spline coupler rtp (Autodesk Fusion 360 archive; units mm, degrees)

design "spline coupler rtp" references "Haas UMC-750 NGC"
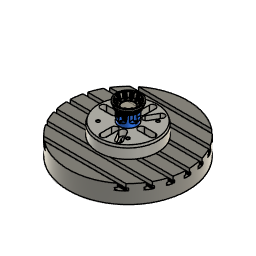
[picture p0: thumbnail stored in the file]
sketch "Sketch1" plane through (0, 0, 0) normal (1, 0, 0) x axis (0, 1, 0)
  line L1 (50.8, 0) -> (0, 0)
  line L2 (50.8, 25.4) -> (50.8, 0)
  line L3 (44.45, 25.4) -> (50.8, 25.4)
  line L4 (37.5164, 6.35) -> (44.45, 25.4)
  line L5 (0, 6.35) -> (37.5164, 6.35)
  line L6 (0, 0) -> (0, 6.35)
  line L7 (50.8, 19.05) -> (50.8, 25.4)
  line L8 (43.8664, 0) -> (50.8, 19.05)
  line L9 (48.0144, 13.7174) -> (48.4888, 12.7)
  line L10 (49.0317, 14.1918) -> (48.0144, 13.7174)
  line L11 (48.7603, 13.4459) -> (48.0144, 13.7174)
  line L12 (46.1776, 6.35) -> (47.0031, 6.35)
  circle C1 centre (48.9975, 12.9372) radius 0.5613
  circle C2 centre (47.0031, 6.35) radius 1.5875
  point P1 (0, 0)
  point P2 (0, 0)
  point P8 (0, 0)
  point P9 (50.8, 19.05)
  point P10 (43.8664, 0)
  point P11 (48.4888, 12.7)
  point P13 (49.0317, 14.1918)
  point P14 (48.7603, 13.4459)
  point P16 (48.4888, 12.7)
  point P17 (48.7603, 13.4459)
  point P18 (47.0031, 6.35)
  point P19 (47.0031, 6.35)
  point P20 (46.1776, 6.35)
  point P3 (50.8, 0)
  point P4 (50.8, 25.4)
  point P7 (0, 6.35)
  point P12 (48.0144, 13.7174)
  point P5 (44.45, 25.4)
  coincident P1 P2
  horizontal L1
  perpendicular L1 L2
  perpendicular L2 L3
  parallel L1 L5
  coincident P1 P8
  vertical L6
  coincident L2 P9
  coincident L1 P10
  parallel L4 L8
  coincident L8 P11
  coincident L8 P13
  perpendicular L9 L10
  equal L9 L10
  coincident L8 P14
  perpendicular L8 L11
  coincident C1 P16
  coincident L8 P16
  coincident P11 P16
  coincident C1 P17
  coincident P14 P17
  tangent L9 C1
  coincident P18 P19
  coincident L8 P20
  horizontal L12
  dimension "d2" = 88.9
  dimension "d3" distance P3 P4 = 25.4
  dimension "d4" angle L3 L4 = 70
  dimension "d5" distance P7 P8 = 6.35
  dimension "d37" distance P4 P9 = 6.35
  dimension "d38" distance P12 P14 = 0.7937
  dimension "d39" distance P10 P11 = 12.7
  dimension "d40" distance P4 P5 = 6.35
  dimension "d43" diameter C2 = 3.175
  dimension "d44" distance L1 P18 = 6.35
  dimension "d45" distance P19 P20 = 0.8255
revolve "Revolve1" sketch "Sketch1" AlongAngle 360
work_plane "WorkPlane1" AlongDistance -3.175
sketch "Sketch2" plane through (0, 0, 22.225) normal (0, 0, 1) x axis (1, 0, 0)
  line L1 (0, 36.9444) -> (0, 0)
  line L2 (3.175, 36.9444) -> (-3.175, 36.9444)
  line L3 (3.175, 32.5535) -> (3.175, 36.9444)
  circle C1 centre (0, 0) radius 43.2944
  circle C2 centre (0, 0) radius 36.9444
  arc A1 centre (10.795, 36.9444) radius 7.62 clockwise from (3.175, 36.9444) to (6.0106, 42.8751)
  arc A2 centre (-10.795, 36.9444) radius 7.62 clockwise from (-6.0106, 42.8751) to (-3.175, 36.9444)
  point P2 (0, 0)
  point P4 (0, 0)
  point P5 (0, 36.9444)
  point P8 (6.0106, 42.8751)
  point P7 (3.175, 36.9444)
  point P13 (-3.175, 36.9444)
  point P12 (-6.0106, 42.8751)
  point P6 (-3.175, 36.9444)
  coincident P2 P4
  coincident C2 P5
  vertical L1
  perpendicular L1 L2
  midpoint P5 L2
  coincident C1 P8
  perpendicular L2 L3
  tangent A1 L3
  symmetric L1 P7 P13
  symmetric L1 P8 P12
  symmetric L1 A1 A2
  dimension "d8" = 6.35
  dimension "d9" distance P6 P7 = 6.35
  dimension "d10" radius A1 = 7.62
sketch "Sketch3" plane through (0, 0, 22.225) normal (0, 0, 1) x axis (1, 0, 0)
sketch "Sketch4" plane through (0, 0, 0) normal (1, 0, 0) x axis (0, 1, 0)
  line L1 (37.5164, 6.35) -> (44.45, 25.4)
  line L2 (-44.45, 25.4) -> (-37.5164, 6.35)
  line L3 (36.9444, 22.225) -> (0, 22.225)
  line L4 (31.1664, 6.35) -> (36.9444, 22.225)
  line L5 (-37.5164, 6.35) -> (37.5164, 6.35)
  point P7 (36.9444, 22.225)
  point P8 (36.9444, 22.225)
  point P9 (31.1664, 6.35)
  coincident P7 P8
  coincident P9 L5
  parallel L1 L4
copy_paste_bodies "CopyPasteBodies2"
sweep "Sweep1" sketch "Sketch2" TwistAngle 0 TaperAngle 0
fillet "Fillet1" sketch "Sketch1" radius 1.5875
fillet "Fillet5" sketch "Sketch1" radius 1.5875
circular_pattern "C-Pattern1" countU 12 TotalAngle 360
fillet "Fillet2" radius 1.5875
fillet "Fillet4" radius 1.5875
sketch "Sketch5" plane through (0, 0, 6.35) normal (0, 0, 1) x axis (-1, 0, 0)
  curve K1 (12.3507, -34.2457) -> (12.1885, -30.8252)
  line L1 (16.5345, -25.1581) -> (13.5203, -26.8984)
  curve K2 (20.6012, -25.9681) -> (23.4823, -27.8189)
  curve K3 (27.8189, -23.4823) -> (25.9681, -20.6012)
  line L2 (26.8984, -13.5203) -> (25.1581, -16.5345)
  curve K4 (30.8252, -12.1885) -> (34.2457, -12.3507)
  curve K5 (35.833, -6.4268) -> (32.7897, -4.8571)
  line L3 (30.0548, 1.7403) -> (30.0548, -1.7403)
  curve K6 (32.7897, 4.8571) -> (35.833, 6.4268)
  curve K7 (34.2457, 12.3507) -> (30.8252, 12.1885)
  line L4 (25.1581, 16.5345) -> (26.8984, 13.5203)
  curve K8 (25.9681, 20.6012) -> (27.8189, 23.4823)
  curve K9 (23.4823, 27.8189) -> (20.6012, 25.9681)
  line L5 (13.5203, 26.8984) -> (16.5345, 25.1581)
  curve K10 (12.1885, 30.8252) -> (12.3507, 34.2457)
  curve K11 (6.4268, 35.833) -> (4.8571, 32.7897)
  line L6 (-1.7403, 30.0548) -> (1.7403, 30.0548)
  curve K12 (-4.8571, 32.7897) -> (-6.4268, 35.833)
  curve K13 (-12.3507, 34.2457) -> (-12.1885, 30.8252)
  line L7 (-16.5345, 25.1581) -> (-13.5203, 26.8984)
  curve K14 (-20.6012, 25.9681) -> (-23.4823, 27.8189)
  curve K15 (-27.8189, 23.4823) -> (-25.9681, 20.6012)
  line L8 (-26.8984, 13.5203) -> (-25.1581, 16.5345)
  curve K16 (-30.8252, 12.1885) -> (-34.2457, 12.3507)
  curve K17 (-35.833, 6.4268) -> (-32.7897, 4.8571)
  line L9 (-30.0548, -1.7403) -> (-30.0548, 1.7403)
  curve K18 (-32.7897, -4.8571) -> (-35.833, -6.4268)
  curve K19 (-34.2457, -12.3507) -> (-30.8252, -12.1885)
  line L10 (-25.1581, -16.5345) -> (-26.8984, -13.5203)
  curve K20 (-25.9681, -20.6012) -> (-27.8189, -23.4823)
  curve K21 (-23.4823, -27.8189) -> (-20.6012, -25.9681)
  line L11 (-13.5203, -26.8984) -> (-16.5345, -25.1581)
  curve K22 (-12.1885, -30.8252) -> (-12.3507, -34.2457)
  curve K23 (-6.4268, -35.833) -> (-4.8571, -32.7897)
  line L12 (1.7403, -30.0548) -> (-1.7403, -30.0548)
  curve K24 (4.8571, -32.7897) -> (6.4268, -35.833)
  closed curve K25 centre (15.2096, -29.8245)
  closed curve K26 centre (18.2239, -28.0842)
  arc A1 centre (0, 0) radius 36.4048 clockwise from (27.8189, -23.4823) to (23.4823, -27.8189)
  closed curve K27 centre (28.0842, -18.2239)
  closed curve K28 centre (29.8245, -15.2096)
  arc A2 centre (0, 0) radius 36.4048 clockwise from (35.833, -6.4268) to (34.2457, -12.3507)
  closed curve K29 centre (33.4336, -1.7403)
  closed curve K30 centre (33.4336, 1.7403)
  arc A3 centre (0, 0) radius 36.4048 clockwise from (34.2457, 12.3507) to (35.833, 6.4268)
  closed curve K31 centre (29.8245, 15.2096)
  closed curve K32 centre (28.0842, 18.2239)
  arc A4 centre (0, 0) radius 36.4048 clockwise from (23.4823, 27.8189) to (27.8189, 23.4823)
  closed curve K33 centre (18.2239, 28.0842)
  closed curve K34 centre (15.2096, 29.8245)
  arc A5 centre (0, 0) radius 36.4048 clockwise from (6.4268, 35.833) to (12.3507, 34.2457)
  closed curve K35 centre (1.7403, 33.4336)
  closed curve K36 centre (-1.7403, 33.4336)
  arc A6 centre (0, 0) radius 36.4048 clockwise from (-12.3507, 34.2457) to (-6.4268, 35.833)
  closed curve K37 centre (-15.2096, 29.8245)
  closed curve K38 centre (-18.2239, 28.0842)
  arc A7 centre (0, 0) radius 36.4048 clockwise from (-27.8189, 23.4823) to (-23.4823, 27.8189)
  closed curve K39 centre (-28.0842, 18.2239)
  closed curve K40 centre (-29.8245, 15.2096)
  arc A8 centre (0, 0) radius 36.4048 clockwise from (-35.833, 6.4268) to (-34.2457, 12.3507)
  closed curve K41 centre (-33.4336, 1.7403)
  closed curve K42 centre (-33.4336, -1.7403)
  arc A9 centre (0, 0) radius 36.4048 clockwise from (-34.2457, -12.3507) to (-35.833, -6.4268)
  closed curve K43 centre (-29.8245, -15.2096)
  closed curve K44 centre (-28.0842, -18.2239)
  arc A10 centre (0, 0) radius 36.4048 clockwise from (-23.4823, -27.8189) to (-27.8189, -23.4823)
  closed curve K45 centre (-18.2239, -28.0842)
  closed curve K46 centre (-15.2096, -29.8245)
  arc A11 centre (0, 0) radius 36.4048 clockwise from (-6.4268, -35.833) to (-12.3507, -34.2457)
  closed curve K47 centre (-1.7403, -33.4336)
  closed curve K48 centre (1.7403, -33.4336)
  arc A12 centre (0, 0) radius 36.4048 clockwise from (12.3507, -34.2457) to (6.4268, -35.833)
  circle C1 centre (0, 0) radius 25.4
  concentric A1 C1
  dimension "d29" diameter C1 = 50.8
extrude "Extrude1" cut sketch "Sketch5" profile of C1 against normal blind 3.175
chamfer "Chamfer1" sketch "Sketch1" distance 0.7937
fillet "Fillet6" sketch "Sketch1" radius 1.5875
delete_face "DeleteFace1"
delete_face "DeleteFace2"
delete_face "DeleteFace3"
derived_base_feature "Derived Base Feature1" bodies "Dovetail"
move "Move1"
offset_faces "OffsetFaces1" distance -25.4
move "Move2"
align "Align1"
combine "Combine2" bodies "Dovetail"
derived_base_feature "Derived Base Feature1" bodies "Body1"
base_feature "Base Feature1"
joint "Assemble1" alignAngle 0 alignOffsetX 0 named "d2_1" alignOffsetY 0 named "d3_1" alignOffsetZ 0 named "d4_1"
base_feature "Base Feature1" bodies "Body1", "Body2", "Body3", "Body4", "Body5", "Body6"
joint "Assemble2" alignAngle 0 named "d5_1" alignOffsetX 0 named "d6_1" alignOffsetY 0 named "d7_1" alignOffsetZ 0 named "d8_1"
joint "Assemble1" alignAngle 0 alignOffsetX 0 alignOffsetY 0 alignOffsetZ 0
sketch "Sketch7" plane through (0, 0, 0) normal (1, 0, 0) x axis (0, 1, 0)
  line L1 (-251.1903, -101.5746) -> (-198.6319, -101.5746)
  point P1 (0, 0)
  point P2 (0, -355.5746)
  vertical P1 P2
  dimension "d51" distance P2 L1 = 254
work_point "WorkPoint1"
sketch "Dovetail" plane through (0, 0, 0) normal (1, 0, 0) x axis (0, 1, 0)
  line L1 (-18.5336, -2.3876) -> (-17.1551, 0)
  line L2 (-18.5336, -3.1496) -> (-18.5336, -2.3876)
  line L3 (-23.5051, 0) -> (-17.1551, 0)
  line L4 (-23.5051, -50.8) -> (-23.5051, 0)
  line L5 (-18.5336, -50.8) -> (-23.5051, -50.8)
  line L6 (-18.5336, -3.1496) -> (-18.5336, -50.8)
  point P2 (-17.1551, 0)
  point P6 (-17.1551, 0)
  point P5 (-18.5336, -3.1496)
  point P10 (-18.5336, -3.1496)
  point P7 (-23.5051, 0)
  point P8 (-23.5051, -50.8)
  coincident P2 P6
  horizontal L3
  perpendicular L3 L4
  perpendicular L4 L5
  coincident P5 P10
  vertical L6
  dimension "d52" = 12.7
  dimension "d53" distance P7 P8 = 50.8
sketch "Sketch9" plane through (0, 0, 0) normal (1, 0, 0) x axis (0, 1, 0)
  line L1 (31.5465, 7.3945) -> (36.5642, 21.1805)
revolve "Revolve3" AlongAngle 360
component_insert "Component Insert"
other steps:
base_feature "Base Feature2" bodies "Stock"
joint_origin "JointOrigin1"
create_component "CreateComponent1"
joint_origin "JointOrigin1"
create_component "CreateComponent2"
create_component "CreateComponent2"
create_component "CreateComponent3"
named bodies: "Part", "Stock", "Dovetail", "Body1", "Body2", "Body3", "Body4", "Body5", "Body6"

design "Haas UMC-750 NGC"
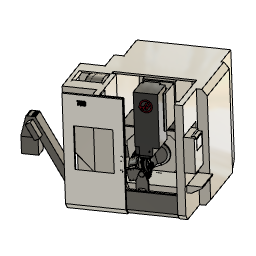
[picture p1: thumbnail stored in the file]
base_feature "Base Feature1"
base_feature "Base Feature1"
base_feature "Base Feature1"
base_feature "Base Feature1"
base_feature "Base Feature1"
base_feature "Base Feature1"
base_feature "Base Feature1"
base_feature "Base Feature1"
base_feature "Base Feature1" bodies "Body1"
base_feature "Base Feature1"
base_feature "Base Feature1" bodies "Body1", "Body2", "Body3", "Body4", "Body5", "Body6"
joint "Assemble1" alignAngle 0 alignOffsetX 0 alignOffsetY 0 alignOffsetZ 0
joint "Assemble2" alignAngle 0 alignOffsetX 0 alignOffsetY 0 alignOffsetZ 0
as_built_joint "As-built1"
as_built_joint "As-built2" OffsetX 0 OffsetY 0 OffsetZ 0 AngleZ 0
as_built_joint "As-built3" OffsetX 0 OffsetY 0 OffsetZ 0 AngleZ 0
ground "Ground1"
ground "Ground2"
sketch "Sketch1" plane through (0, 0, 0) normal (1, 0, 0) x axis (0, 1, 0)
  line L1 (50.8, 0) -> (0, 0)
  line L2 (50.8, 25.4) -> (50.8, 0)
  line L3 (44.45, 25.4) -> (50.8, 25.4)
  line L4 (37.5164, 6.35) -> (44.45, 25.4)
  line L5 (0, 6.35) -> (37.5164, 6.35)
  line L6 (0, 0) -> (0, 6.35)
  line L7 (50.8, 19.05) -> (50.8, 25.4)
  line L8 (43.8664, 0) -> (50.8, 19.05)
  line L9 (48.0144, 13.7174) -> (48.4888, 12.7)
  line L10 (49.0317, 14.1918) -> (48.0144, 13.7174)
  line L11 (48.7603, 13.4459) -> (48.0144, 13.7174)
  line L12 (46.1776, 6.35) -> (47.0031, 6.35)
  circle C1 centre (48.9975, 12.9372) radius 0.5613
  circle C2 centre (47.0031, 6.35) radius 1.5875
  point P1 (0, 0)
  point P2 (0, 0)
  point P8 (0, 0)
  point P9 (50.8, 19.05)
  point P10 (43.8664, 0)
  point P11 (48.4888, 12.7)
  point P13 (49.0317, 14.1918)
  point P14 (48.7603, 13.4459)
  point P16 (48.4888, 12.7)
  point P17 (48.7603, 13.4459)
  point P18 (47.0031, 6.35)
  point P19 (47.0031, 6.35)
  point P20 (46.1776, 6.35)
  point P3 (50.8, 0)
  point P4 (50.8, 25.4)
  point P7 (0, 6.35)
  point P12 (48.0144, 13.7174)
  point P5 (44.45, 25.4)
  coincident P1 P2
  horizontal L1
  perpendicular L1 L2
  perpendicular L2 L3
  parallel L1 L5
  coincident P1 P8
  vertical L6
  coincident L2 P9
  coincident L1 P10
  parallel L4 L8
  coincident L8 P11
  coincident L8 P13
  perpendicular L9 L10
  equal L9 L10
  coincident L8 P14
  perpendicular L8 L11
  coincident C1 P16
  coincident L8 P16
  coincident P11 P16
  coincident C1 P17
  coincident P14 P17
  tangent L9 C1
  coincident P18 P19
  coincident L8 P20
  horizontal L12
  dimension "d2_1" = 88.9
  dimension "d3_1" distance P3 P4 = 25.4
  dimension "d4_1" angle L3 L4 = 70
  dimension "d5_1" distance P7 P8 = 6.35
  dimension "d37" distance P4 P9 = 6.35
  dimension "d38" distance P12 P14 = 0.7937
  dimension "d39" distance P10 P11 = 12.7
  dimension "d40" distance P4 P5 = 6.35
  dimension "d43" diameter C2 = 3.175
  dimension "d44" distance L1 P18 = 6.35
  dimension "d45" distance P19 P20 = 0.8255
revolve "Revolve1" sketch "Sketch1" AlongAngle 360 named "d6_1"
work_plane "WorkPlane1" AlongDistance -3.175 named "d7_1"
sketch "Sketch2" plane through (0, 0, 22.225) normal (0, 0, 1) x axis (1, 0, 0)
  line L1 (0, 36.9444) -> (0, 0)
  line L2 (3.175, 36.9444) -> (-3.175, 36.9444)
  line L3 (3.175, 32.5535) -> (3.175, 36.9444)
  circle C1 centre (0, 0) radius 43.2944
  circle C2 centre (0, 0) radius 36.9444
  arc A1 centre (10.795, 36.9444) radius 7.62 clockwise from (3.175, 36.9444) to (6.0106, 42.8751)
  arc A2 centre (-10.795, 36.9444) radius 7.62 clockwise from (-6.0106, 42.8751) to (-3.175, 36.9444)
  point P2 (0, 0)
  point P4 (0, 0)
  point P5 (0, 36.9444)
  point P8 (6.0106, 42.8751)
  point P7 (3.175, 36.9444)
  point P13 (-3.175, 36.9444)
  point P12 (-6.0106, 42.8751)
  point P6 (-3.175, 36.9444)
  coincident P2 P4
  coincident C2 P5
  vertical L1
  perpendicular L1 L2
  midpoint P5 L2
  coincident C1 P8
  perpendicular L2 L3
  tangent A1 L3
  symmetric L1 P7 P13
  symmetric L1 P8 P12
  symmetric L1 A1 A2
  dimension "d8_1" = 6.35
  dimension "d9_1" distance P6 P7 = 6.35
  dimension "d10_1" radius A1 = 7.62
sketch "Sketch3" plane through (0, 0, 22.225) normal (0, 0, 1) x axis (1, 0, 0)
sketch "Sketch4" plane through (0, 0, 0) normal (1, 0, 0) x axis (0, 1, 0)
  line L1 (37.5164, 6.35) -> (44.45, 25.4)
  line L2 (-44.45, 25.4) -> (-37.5164, 6.35)
  line L3 (36.9444, 22.225) -> (0, 22.225)
  line L4 (31.1664, 6.35) -> (36.9444, 22.225)
  line L5 (-37.5164, 6.35) -> (37.5164, 6.35)
  point P7 (36.9444, 22.225)
  point P8 (36.9444, 22.225)
  point P9 (31.1664, 6.35)
  coincident P7 P8
  coincident P9 L5
  parallel L1 L4
copy_paste_bodies "CopyPasteBodies2"
sweep "Sweep1" sketch "Sketch2" TwistAngle 0 named "d15_1" TaperAngle 0 named "d16_1"
fillet "Fillet1" radius 1.5875
fillet "Fillet5" radius 1.5875
circular_pattern "C-Pattern1" countU 12 TotalAngle 360
fillet "Fillet2" radius 1.5875
fillet "Fillet4" radius 1.5875
sketch "Sketch5" plane through (0, 0, 6.35) normal (0, 0, 1) x axis (-1, 0, 0)
  curve K1 (12.3507, -34.2457) -> (12.1885, -30.8252)
  line L1 (16.5345, -25.1581) -> (13.5203, -26.8984)
  curve K2 (20.6012, -25.9681) -> (23.4823, -27.8189)
  curve K3 (27.8189, -23.4823) -> (25.9681, -20.6012)
  line L2 (26.8984, -13.5203) -> (25.1581, -16.5345)
  curve K4 (30.8252, -12.1885) -> (34.2457, -12.3507)
  curve K5 (35.833, -6.4268) -> (32.7897, -4.8571)
  line L3 (30.0548, 1.7403) -> (30.0548, -1.7403)
  curve K6 (32.7897, 4.8571) -> (35.833, 6.4268)
  curve K7 (34.2457, 12.3507) -> (30.8252, 12.1885)
  line L4 (25.1581, 16.5345) -> (26.8984, 13.5203)
  curve K8 (25.9681, 20.6012) -> (27.8189, 23.4823)
  curve K9 (23.4823, 27.8189) -> (20.6012, 25.9681)
  line L5 (13.5203, 26.8984) -> (16.5345, 25.1581)
  curve K10 (12.1885, 30.8252) -> (12.3507, 34.2457)
  curve K11 (6.4268, 35.833) -> (4.8571, 32.7897)
  line L6 (-1.7403, 30.0548) -> (1.7403, 30.0548)
  curve K12 (-4.8571, 32.7897) -> (-6.4268, 35.833)
  curve K13 (-12.3507, 34.2457) -> (-12.1885, 30.8252)
  line L7 (-16.5345, 25.1581) -> (-13.5203, 26.8984)
  curve K14 (-20.6012, 25.9681) -> (-23.4823, 27.8189)
  curve K15 (-27.8189, 23.4823) -> (-25.9681, 20.6012)
  line L8 (-26.8984, 13.5203) -> (-25.1581, 16.5345)
  curve K16 (-30.8252, 12.1885) -> (-34.2457, 12.3507)
  curve K17 (-35.833, 6.4268) -> (-32.7897, 4.8571)
  line L9 (-30.0548, -1.7403) -> (-30.0548, 1.7403)
  curve K18 (-32.7897, -4.8571) -> (-35.833, -6.4268)
  curve K19 (-34.2457, -12.3507) -> (-30.8252, -12.1885)
  line L10 (-25.1581, -16.5345) -> (-26.8984, -13.5203)
  curve K20 (-25.9681, -20.6012) -> (-27.8189, -23.4823)
  curve K21 (-23.4823, -27.8189) -> (-20.6012, -25.9681)
  line L11 (-13.5203, -26.8984) -> (-16.5345, -25.1581)
  curve K22 (-12.1885, -30.8252) -> (-12.3507, -34.2457)
  curve K23 (-6.4268, -35.833) -> (-4.8571, -32.7897)
  line L12 (1.7403, -30.0548) -> (-1.7403, -30.0548)
  curve K24 (4.8571, -32.7897) -> (6.4268, -35.833)
  closed curve K25 centre (15.2096, -29.8245)
  closed curve K26 centre (18.2239, -28.0842)
  arc A1 centre (0, 0) radius 36.4048 clockwise from (27.8189, -23.4823) to (23.4823, -27.8189)
  closed curve K27 centre (28.0842, -18.2239)
  closed curve K28 centre (29.8245, -15.2096)
  arc A2 centre (0, 0) radius 36.4048 clockwise from (35.833, -6.4268) to (34.2457, -12.3507)
  closed curve K29 centre (33.4336, -1.7403)
  closed curve K30 centre (33.4336, 1.7403)
  arc A3 centre (0, 0) radius 36.4048 clockwise from (34.2457, 12.3507) to (35.833, 6.4268)
  closed curve K31 centre (29.8245, 15.2096)
  closed curve K32 centre (28.0842, 18.2239)
  arc A4 centre (0, 0) radius 36.4048 clockwise from (23.4823, 27.8189) to (27.8189, 23.4823)
  closed curve K33 centre (18.2239, 28.0842)
  closed curve K34 centre (15.2096, 29.8245)
  arc A5 centre (0, 0) radius 36.4048 clockwise from (6.4268, 35.833) to (12.3507, 34.2457)
  closed curve K35 centre (1.7403, 33.4336)
  closed curve K36 centre (-1.7403, 33.4336)
  arc A6 centre (0, 0) radius 36.4048 clockwise from (-12.3507, 34.2457) to (-6.4268, 35.833)
  closed curve K37 centre (-15.2096, 29.8245)
  closed curve K38 centre (-18.2239, 28.0842)
  arc A7 centre (0, 0) radius 36.4048 clockwise from (-27.8189, 23.4823) to (-23.4823, 27.8189)
  closed curve K39 centre (-28.0842, 18.2239)
  closed curve K40 centre (-29.8245, 15.2096)
  arc A8 centre (0, 0) radius 36.4048 clockwise from (-35.833, 6.4268) to (-34.2457, 12.3507)
  closed curve K41 centre (-33.4336, 1.7403)
  closed curve K42 centre (-33.4336, -1.7403)
  arc A9 centre (0, 0) radius 36.4048 clockwise from (-34.2457, -12.3507) to (-35.833, -6.4268)
  closed curve K43 centre (-29.8245, -15.2096)
  closed curve K44 centre (-28.0842, -18.2239)
  arc A10 centre (0, 0) radius 36.4048 clockwise from (-23.4823, -27.8189) to (-27.8189, -23.4823)
  closed curve K45 centre (-18.2239, -28.0842)
  closed curve K46 centre (-15.2096, -29.8245)
  arc A11 centre (0, 0) radius 36.4048 clockwise from (-6.4268, -35.833) to (-12.3507, -34.2457)
  closed curve K47 centre (-1.7403, -33.4336)
  closed curve K48 centre (1.7403, -33.4336)
  arc A12 centre (0, 0) radius 36.4048 clockwise from (12.3507, -34.2457) to (6.4268, -35.833)
  circle C1 centre (0, 0) radius 25.4
  concentric A1 C1
  dimension "d29" diameter C1 = 50.8
extrude "Extrude1" cut sketch "Sketch5" profile of C1 against normal blind 3.175
chamfer "Chamfer1" distance 0.7937
fillet "Fillet6" radius 1.5875
delete_face "DeleteFace1"
delete_face "DeleteFace2"
delete_face "DeleteFace3"
derived_base_feature "Derived Base Feature1" bodies "Dovetail"
move "Move1"
offset_faces "OffsetFaces1" distance -25.4
move "Move2"
align "Align1"
combine "Combine2" bodies "Dovetail"
derived_base_feature "Derived Base Feature1" bodies "Body1"
base_feature "Base Feature1"
joint "Assemble1" alignAngle 0 named "d1_1" alignOffsetX 0 named "d2_1" alignOffsetY 0 named "d3_1" alignOffsetZ 0 named "d4_1"
base_feature "Base Feature1" bodies "Body1", "Body2", "Body3", "Body4", "Body5", "Body6"
joint "Assemble2" alignAngle 0 named "d5_1" alignOffsetX 0 named "d6_1" alignOffsetY 0 named "d7_1" alignOffsetZ 0 named "d8_1"
joint "Assemble1" alignAngle 0 alignOffsetX 0 alignOffsetY 0 alignOffsetZ 0
sketch "Sketch7" plane through (0, 0, 0) normal (1, 0, 0) x axis (0, 1, 0)
  line L1 (-251.1903, -101.5746) -> (-198.6319, -101.5746)
  point P1 (0, 0)
  point P2 (0, -355.5746)
  vertical P1 P2
  dimension "d51" distance P2 L1 = 254
work_point "WorkPoint1"
sketch "Dovetail" plane through (0, 0, 0) normal (1, 0, 0) x axis (0, 1, 0)
  line L1 (-18.5336, -2.3876) -> (-17.1551, 0)
  line L2 (-18.5336, -3.1496) -> (-18.5336, -2.3876)
  line L3 (-23.5051, 0) -> (-17.1551, 0)
  line L4 (-23.5051, -50.8) -> (-23.5051, 0)
  line L5 (-18.5336, -50.8) -> (-23.5051, -50.8)
  line L6 (-18.5336, -3.1496) -> (-18.5336, -50.8)
  point P2 (-17.1551, 0)
  point P6 (-17.1551, 0)
  point P5 (-18.5336, -3.1496)
  point P10 (-18.5336, -3.1496)
  point P7 (-23.5051, 0)
  point P8 (-23.5051, -50.8)
  coincident P2 P6
  horizontal L3
  perpendicular L3 L4
  perpendicular L4 L5
  coincident P5 P10
  vertical L6
  dimension "d52" = 12.7
  dimension "d53" distance P7 P8 = 50.8
remove_instance "RemoveInstance2"
as_built_joint "As-built4"
as_built_joint "As-built5" OffsetX 0 OffsetY 0 OffsetZ 0 AngleZ 0
ground "Ground3"
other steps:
base_feature "Base Feature2" bodies "Stock"
create_component "CreateComponent1"
create_component "CreateComponent2"
create_component "CreateComponent3"
create_component "CreateComponent4"
create_component "CreateComponent5"
create_component "CreateComponent6"
create_component "CreateComponent7"
create_component "CreateComponent8"
create_component "CreateComponent1"
create_component "CreateComponent2"
create_component "CreateComponent3"
joint_origin "JointOrigin1"
joint_origin "JointOrigin1"
joint_origin "JointOrigin1"
joint_origin "JointOrigin2"
joint_origin "JointOrigin1"
create_component "CreateComponent1"
joint_origin "JointOrigin1"
create_component "CreateComponent2"
create_component "CreateComponent2"
create_component "CreateComponent3"
create_component "CreateComponent9"
named bodies: "Body1", "Body2", "Body3", "Body4", "Body5", "Body6", "Part", "Stock", "Dovetail"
